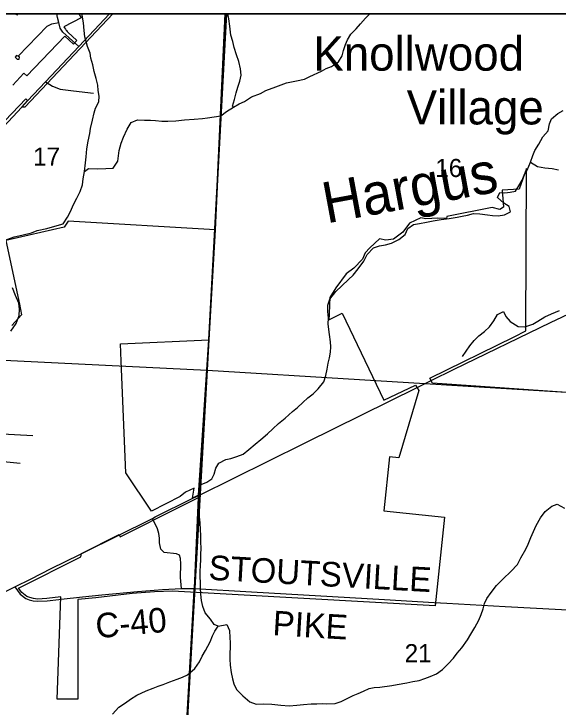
# Model space of a CAD drawing. Extents: x 0 to 42.5, y 0 to 22.
# Drawn here: x 3.26 to 3.889, y 20.099 to 20.9 of the extents above; entities that cross this region are included whole.
import ezdxf

# ---------------------------------------------------------------- set-up
doc = ezdxf.new("R2010")
doc.units = 0
for name, color, linetype in [('Default', 7, 'Continuous'), ('GM_X_City_Street', 7, 'Continuous'), ('GM_X_County_Road', 7, 'Continuous'), ('GM_X_County_Road_Text', 7, 'Continuous'), ('GM_X_Interchange_Ramps', 7, 'Continuous'), ('GM_X_Minor_River', 7, 'Continuous'), ('GM_X_Minor_River_Text', 7, 'Continuous'), ('GM_X_Section', 7, 'Continuous'), ('GM_X_Section_Text', 7, 'Continuous'), ('GM_X_State_Route', 7, 'Continuous'), ('GM_X_Township_Road', 7, 'Continuous'), ('GM_X_Unincorporated', 7, 'Continuous'), ('GM_X_Unincorporated_Text', 7, 'Continuous'), ('GM_X_US_Route', 7, 'Continuous'), ('SH_Cut_Line', 7, 'Continuous'), ('SH_Data', 7, 'Continuous')]:
    doc.layers.add(name, color=color, linetype=linetype)

msp = doc.modelspace()

# ---------------------------------------------------------------- linework, layer by layer
at = {"layer": 'Default'}
for points in [[(3.2411, 20.76833), (3.27355, 20.80191), (3.27571, 20.79986), (3.26896, 20.79269), (3.27265, 20.79246), (3.37429, 20.9), (3.33472, 20.9), (3.3375, 20.89547), (3.3176, 20.88509), (3.31838, 20.88375), (3.3193, 20.88237), (3.31984, 20.88169), (3.32051, 20.88084), (3.32148, 20.87978), (3.32233, 20.87894), (3.33264, 20.86917), (3.32881, 20.86498), (3.31884, 20.87442), (3.27482, 20.82825), (3.27137, 20.83149), (3.2584, 20.81768)], [(4.00978, 20.45475), (3.74365, 20.47336), (3.7405, 20.47906), (3.83808, 20.52698), (3.85138, 20.53367), (3.85232, 20.72132), (3.84367, 20.69748), (3.82404, 20.69631), (3.82568, 20.67669), (3.82124, 20.67411), (3.81259, 20.67622), (3.76025, 20.66594), (3.75987, 20.6636), (3.74959, 20.66407), (3.73604, 20.66337), (3.7302, 20.6643), (3.71711, 20.65822), (3.70917, 20.64794), (3.69842, 20.63976), (3.68954, 20.6386), (3.68229, 20.64), (3.67108, 20.62972), (3.6657, 20.62387), (3.66266, 20.61663), (3.65262, 20.60611), (3.64374, 20.59957), (3.63205, 20.58368), (3.62481, 20.57247), (3.62457, 20.56405), (3.62434, 20.55307), (3.62364, 20.54676), (3.63906, 20.55424), (3.6872, 20.45369), (3.72412, 20.47121), (3.72782, 20.46511), (3.70483, 20.38711), (3.69408, 20.38843), (3.68752, 20.32599), (3.75748, 20.31864), (3.74672, 20.21626), (3.44312, 20.23308), (3.42248, 20.23249), (3.39652, 20.23042), (3.35444, 20.22544), (3.33357, 20.2236), (3.33356, 20.10854), (3.30981, 20.10854), (3.31398, 20.22648), (3.29803, 20.22467), (3.28725, 20.22405), (3.28256, 20.22458), (3.27824, 20.2257), (3.27489, 20.22715), (3.2688, 20.23176), (3.26515, 20.23666), (3.33718, 20.27273), (3.33776, 20.27671), (3.38143, 20.29841), (3.38253, 20.29579), (3.45331, 20.33129), (3.47315, 20.34124), (3.47328, 20.34399), (3.46615, 20.34046), (3.46806, 20.35207), (3.45818, 20.34746), (3.45205, 20.34247), (3.41868, 20.32574), (3.38918, 20.36973), (3.38374, 20.49883), (3.3829, 20.51877), (3.48511, 20.52333), (3.49253, 20.65067), (3.32237, 20.66037), (3.31781, 20.65352), (3.25043, 20.6381), (3.2661, 20.56466), (3.2687, 20.55245), (3.25728, 20.53989)]]:
    msp.add_lwpolyline(points, dxfattribs=at)
at = {"layer": 'GM_X_City_Street'}
for points in [[(3.16393, 20.41928), (3.19651, 20.41749), (3.28161, 20.41282)], [(3.1975, 20.38464), (3.25158, 20.38246), (3.26694, 20.38101)]]:
    msp.add_lwpolyline(points, dxfattribs=at)
at = {"layer": 'GM_X_County_Road'}
msp.add_line((3.3143, 20.22385), (3.33918, 20.22644), dxfattribs=at)
for points in [[(3.26093, 20.2382), (3.26722, 20.22981), (3.2738, 20.22483), (3.27757, 20.22319), (3.28223, 20.22198), (3.2873, 20.22141), (3.29835, 20.22204), (3.31181, 20.2236), (3.3143, 20.22385)], [(3.33918, 20.22644), (3.36158, 20.22877), (3.40255, 20.23263), (3.43172, 20.23516), (3.45359, 20.23608), (3.46349, 20.2362)], [(3.46349, 20.2362), (3.46843, 20.23625), (3.53455, 20.23246), (3.68806, 20.22342), (3.7457, 20.22016)], [(3.7457, 20.22016), (3.7601, 20.21934), (3.82766, 20.21554), (3.92139, 20.21048), (3.97179, 20.2072), (3.97328, 20.20712)]]:
    msp.add_lwpolyline(points, dxfattribs=at)
at = {"layer": 'GM_X_Interchange_Ramps'}
for points in [[(3.11995, 19.00104), (3.37078, 18.98615), (3.37742, 18.98467), (3.39197, 18.98393), (3.40756, 19.23914), (3.43715, 19.68433), (3.46832, 20.23391), (3.46843, 20.23651), (3.47315, 20.34124), (3.47328, 20.34399), (3.48511, 20.52333), (3.49253, 20.65067), (3.50401, 20.9), (2.3057, 20.9)], [(5.48884, 19.405), (5.50057, 19.55251), (5.51061, 19.66936), (5.5156, 19.73605), (5.52526, 19.85376), (5.53536, 19.98472), (5.54606, 20.11658), (5.56474, 20.34561), (5.56563, 20.35496), (5.56586, 20.35729), (5.60252, 20.8068), (5.60957, 20.9), (3.50401, 20.9), (3.49253, 20.65067), (3.48511, 20.52333), (3.47328, 20.34399), (3.47315, 20.34124), (3.46843, 20.23651), (3.46832, 20.23391), (3.43715, 19.68433), (3.40756, 19.23914)]]:
    msp.add_lwpolyline(points, dxfattribs=at)
at = {"layer": 'GM_X_Minor_River'}
for points in [[(3.34425, 20.74395), (3.34563, 20.75287), (3.34739, 20.76179), (3.34819, 20.76749), (3.35071, 20.77717), (3.35246, 20.78552), (3.3542, 20.79102), (3.35804, 20.7984), (3.35846, 20.80486), (3.35736, 20.81133), (3.35683, 20.8178), (3.35498, 20.82541), (3.35257, 20.83341), (3.35091, 20.84102), (3.34887, 20.84882), (3.34815, 20.85472), (3.34497, 20.86234), (3.34163, 20.87339), (3.34091, 20.88061), (3.34021, 20.88955), (3.33856, 20.89868), (3.33813, 20.9)], [(3.34125, 20.71793), (3.3462, 20.72151), (3.35643, 20.72088), (3.3661, 20.72119), (3.37463, 20.72171), (3.37979, 20.72966), (3.38078, 20.73611), (3.38138, 20.742), (3.38371, 20.75073), (3.38659, 20.75755), (3.39082, 20.76684), (3.39522, 20.7746), (3.40282, 20.77759), (3.41078, 20.77716), (3.41779, 20.7773), (3.42347, 20.77689), (3.43066, 20.77608), (3.43768, 20.77604), (3.44696, 20.77655), (3.45682, 20.77762), (3.46801, 20.77831), (3.47787, 20.7792), (3.48355, 20.77973), (3.49114, 20.78101), (3.49892, 20.78229), (3.50558, 20.78738), (3.51357, 20.79227), (3.52022, 20.79603), (3.5263, 20.79884), (3.53429, 20.8043), (3.54493, 20.80785), (3.55101, 20.81161), (3.5626, 20.81571), (3.57494, 20.82019), (3.58651, 20.82259), (3.59562, 20.82462), (3.6017, 20.82762), (3.61538, 20.83362), (3.62089, 20.837), (3.62678, 20.83925), (3.63477, 20.84452), (3.63918, 20.85171), (3.64073, 20.85759), (3.64304, 20.86461), (3.64535, 20.8701), (3.64937, 20.87673), (3.65528, 20.88258), (3.66043, 20.88863), (3.66634, 20.89506), (3.67103, 20.9)], [(3.51357, 20.79227), (3.51263, 20.79323), (3.51495, 20.80101), (3.5167, 20.80879), (3.51863, 20.81524), (3.52095, 20.82244), (3.52232, 20.82908), (3.52179, 20.83669), (3.51976, 20.84487), (3.51716, 20.85268), (3.51455, 20.86125), (3.5127, 20.8681), (3.51066, 20.87534), (3.50921, 20.88561), (3.50812, 20.89417), (3.50693, 20.9)], [(3.84328, 20.70122), (3.84711, 20.70803), (3.84941, 20.71353), (3.85305, 20.71959), (3.85671, 20.72888), (3.85941, 20.73627), (3.8619, 20.74215), (3.86631, 20.74953), (3.87128, 20.75805), (3.8772, 20.76485), (3.87895, 20.77301), (3.88107, 20.77889), (3.88831, 20.78474), (3.89478, 20.7885)], [(3.24848, 20.63814), (3.26026, 20.64244), (3.26899, 20.64447), (3.28019, 20.64706), (3.28664, 20.64968), (3.29784, 20.65208), (3.30714, 20.65468), (3.31682, 20.65747), (3.3216, 20.66523), (3.32505, 20.67167), (3.32851, 20.67963), (3.33273, 20.68701), (3.33657, 20.69497), (3.33907, 20.70236), (3.34006, 20.70939), (3.34125, 20.71793), (3.34264, 20.72781), (3.34325, 20.73502), (3.34425, 20.74395)], [(3.85671, 20.72888), (3.86482, 20.7235), (3.87353, 20.72231), (3.88186, 20.7213), (3.88905, 20.71993)], [(3.4959, 20.1928), (3.49137, 20.19473), (3.48705, 20.20084), (3.48084, 20.20829), (3.47823, 20.21553), (3.47675, 20.22238), (3.47604, 20.2298), (3.47552, 20.23702), (3.47536, 20.24272), (3.47522, 20.25014), (3.47525, 20.25584), (3.47548, 20.26287), (3.47571, 20.26933), (3.47575, 20.27617), (3.47617, 20.28206), (3.47603, 20.29042), (3.47569, 20.29726), (3.47536, 20.30449), (3.47521, 20.3119), (3.4745, 20.31894), (3.47416, 20.32578), (3.4742, 20.33167), (3.47405, 20.33775), (3.47408, 20.34346), (3.47431, 20.34992), (3.47624, 20.35655), (3.48289, 20.35898), (3.4886, 20.36275), (3.49128, 20.36824), (3.49322, 20.37507), (3.49667, 20.38094), (3.50484, 20.38526), (3.51072, 20.38655), (3.51737, 20.38879), (3.52496, 20.3914), (3.53144, 20.39687), (3.53868, 20.4029), (3.54515, 20.40837), (3.55277, 20.41498), (3.55906, 20.42083), (3.56554, 20.42687), (3.57316, 20.43309), (3.58173, 20.44083), (3.58763, 20.44535), (3.59373, 20.4512), (3.59963, 20.45629), (3.60554, 20.4612), (3.61145, 20.46686), (3.61794, 20.4748), (3.62026, 20.48239), (3.62182, 20.4896), (3.62318, 20.49643), (3.62474, 20.50269), (3.62553, 20.50915), (3.62595, 20.51523), (3.62561, 20.52131), (3.62471, 20.52949), (3.6238, 20.53558), (3.62308, 20.54204), (3.6235, 20.5485), (3.6226, 20.5563), (3.62264, 20.56352), (3.62477, 20.57035), (3.63184, 20.57943), (3.6387, 20.58603), (3.64651, 20.5932), (3.65203, 20.59811), (3.65757, 20.6053), (3.66407, 20.61438), (3.6681, 20.62214), (3.67534, 20.6297), (3.68218, 20.63193), (3.68939, 20.63303), (3.69622, 20.63507), (3.70477, 20.6392), (3.71201, 20.64524), (3.71527, 20.65225), (3.72155, 20.65677), (3.72857, 20.65786), (3.73653, 20.65933), (3.74431, 20.66099), (3.75361, 20.66264), (3.76271, 20.66372), (3.772, 20.665), (3.77807, 20.66629), (3.78395, 20.66758), (3.79117, 20.66943), (3.79836, 20.66901), (3.80726, 20.66781), (3.81313, 20.6672), (3.81957, 20.66659), (3.82678, 20.66787), (3.83362, 20.67125), (3.83233, 20.67753), (3.82591, 20.68118), (3.81856, 20.68769), (3.82144, 20.69375), (3.82712, 20.69334), (3.83338, 20.69406), (3.83964, 20.69535), (3.84328, 20.70122)], [(3.25638, 20.53357), (3.2623, 20.54227), (3.26596, 20.55156), (3.26619, 20.55878), (3.26567, 20.56563), (3.26174, 20.57458), (3.25801, 20.58354)], [(3.77823, 20.50418), (3.78262, 20.51042), (3.78683, 20.51648), (3.79179, 20.52253), (3.79713, 20.52819), (3.8036, 20.53309), (3.80932, 20.53838), (3.81448, 20.54557), (3.81869, 20.55257), (3.82572, 20.55614), (3.82853, 20.55023), (3.83342, 20.54449), (3.84248, 20.53892), (3.85044, 20.53849), (3.85936, 20.54148), (3.86525, 20.54486), (3.87343, 20.54994), (3.88103, 20.55369), (3.89034, 20.55724)], [(3.71379, 20.12736), (3.721, 20.12883), (3.72801, 20.13012), (3.73485, 20.13235), (3.74074, 20.13441), (3.74814, 20.13759), (3.75518, 20.14248), (3.76167, 20.14909), (3.76777, 20.15571), (3.77197, 20.16138), (3.77751, 20.16781), (3.7842, 20.17708), (3.78802, 20.18332), (3.79262, 20.19128), (3.79722, 20.1998), (3.79991, 20.20624), (3.80204, 20.21288), (3.80359, 20.21895), (3.80628, 20.22482), (3.81143, 20.23144), (3.81755, 20.23958), (3.82517, 20.24732), (3.83413, 20.25581), (3.84176, 20.26413), (3.84578, 20.27151), (3.85134, 20.28174), (3.85403, 20.28742), (3.8573, 20.29519), (3.86018, 20.30221), (3.86325, 20.30884), (3.86823, 20.31774), (3.87396, 20.3253), (3.88139, 20.33134), (3.88766, 20.33377), (3.89634, 20.32915)], [(3.37382, 20.09096), (3.38107, 20.09928), (3.38868, 20.10417), (3.39439, 20.1085), (3.402, 20.11302), (3.41283, 20.11789), (3.42062, 20.12107), (3.4267, 20.12331), (3.43239, 20.12536), (3.44018, 20.12835), (3.44835, 20.13153), (3.4548, 20.13377), (3.46032, 20.1364), (3.46908, 20.14375), (3.47424, 20.15151), (3.4775, 20.15814), (3.48133, 20.16458), (3.48651, 20.17443), (3.48939, 20.18144), (3.49189, 20.18694), (3.4959, 20.1928), (3.50577, 20.19483), (3.50894, 20.18759), (3.50927, 20.17941), (3.50981, 20.1739), (3.50978, 20.16839), (3.50935, 20.16117), (3.50931, 20.15452), (3.50984, 20.14748), (3.51073, 20.13911), (3.5124, 20.13207), (3.51407, 20.12598), (3.51725, 20.11969), (3.5244, 20.11223), (3.53251, 20.10515), (3.53969, 20.10263), (3.5486, 20.10314), (3.55788, 20.10251), (3.56849, 20.1013), (3.57777, 20.10086), (3.58687, 20.10138), (3.59445, 20.10228), (3.60355, 20.10298), (3.60999, 20.10313), (3.61606, 20.10328), (3.62155, 20.10305), (3.63103, 20.10337), (3.63805, 20.10561), (3.64508, 20.10917), (3.65174, 20.11274), (3.65782, 20.11498), (3.6639, 20.11779), (3.67036, 20.1206), (3.67605, 20.12171), (3.68268, 20.12243), (3.69671, 20.12424), (3.70278, 20.12515), (3.71379, 20.12736)]]:
    msp.add_lwpolyline(points, dxfattribs=at)
at = {"layer": 'GM_X_Section'}
for points in [[(2.97397, 20.51334), (3.48334, 20.48855), (3.4546, 19.98469), (2.94222, 20.01405)], [(3.48334, 20.48855), (4.01124, 20.45591), (3.97586, 19.95227), (3.4546, 19.98469)]]:
    msp.add_lwpolyline(points, close=True, dxfattribs=at)
at = {"layer": 'GM_X_State_Route'}
msp.add_line((3.2688, 20.79213), (3.27571, 20.79948), dxfattribs=at)
for points in [[(3.27571, 20.79948), (3.29644, 20.82154), (3.33468, 20.86223), (3.37048, 20.9)], [(3.17387, 20.72882), (3.21945, 20.75311), (3.24254, 20.76419), (3.2688, 20.79213)]]:
    msp.add_lwpolyline(points, dxfattribs=at)
at = {"layer": 'GM_X_Township_Road'}
for points in [[(3.26089, 20.9), (3.26402, 20.89904), (3.26424, 20.9)], [(3.33468, 20.86223), (3.3162, 20.87896), (3.31338, 20.88354), (3.31168, 20.8901), (3.31022, 20.89572), (3.30946, 20.9)], [(3.26458, 20.85113), (3.26286, 20.85206), (3.26139, 20.85007), (3.26354, 20.84749), (3.26596, 20.8476), (3.26612, 20.84986), (3.26468, 20.85113), (3.29821, 20.88591), (3.30373, 20.88854), (3.31168, 20.8901)], [(3.29644, 20.82154), (3.30426, 20.8165), (3.31336, 20.81303), (3.32854, 20.81123), (3.3517, 20.80843)], [(3.45359, 20.23608), (3.45219, 20.24907), (3.45285, 20.26484), (3.4525, 20.27092), (3.45139, 20.27473), (3.44779, 20.27646), (3.43355, 20.27788), (3.42969, 20.28168), (3.42826, 20.28896), (3.4279, 20.29445), (3.42726, 20.29973), (3.42562, 20.3053), (3.41997, 20.31725)]]:
    msp.add_lwpolyline(points, dxfattribs=at)
at = {"layer": 'GM_X_Unincorporated'}
for points in [[(3.50543, 20.9), (2.99274, 20.9), (2.97397, 20.51334), (3.48334, 20.48855)], [(4.04384, 20.9), (3.50543, 20.9), (3.48334, 20.48855), (4.01124, 20.45591)]]:
    msp.add_lwpolyline(points, close=True, dxfattribs=at)
at = {"layer": 'GM_X_US_Route'}
for p, q in [((3.72597, 20.46833), (3.74212, 20.47632)), ((3.47339, 20.34373), (3.59496, 20.40355)), ((3.46667, 20.3404), (3.47339, 20.34373)), ((3.3382, 20.27661), (3.38176, 20.29825)), ((3.33586, 20.27544), (3.3382, 20.27661)), ((3.30308, 20.25915), (3.33586, 20.27544)), ((3.27966, 20.24751), (3.30308, 20.25915))]:
    msp.add_line(p, q, dxfattribs=at)
for points in [[(3.74212, 20.47632), (3.76859, 20.48941), (3.88009, 20.54365), (3.91506, 20.56001), (3.95465, 20.57598), (4.02129, 20.60145)], [(3.59496, 20.40355), (3.5981, 20.40509), (3.72597, 20.46833)], [(3.38176, 20.29825), (3.41688, 20.31571), (3.41997, 20.31725), (3.42322, 20.31886), (3.46667, 20.3404)], [(3.21026, 20.21284), (3.26093, 20.2382), (3.27966, 20.24751)]]:
    msp.add_lwpolyline(points, dxfattribs=at)
at = {"layer": 'SH_Cut_Line'}
msp.add_lwpolyline([(5.48884, 19.405), (5.50057, 19.55251), (5.51061, 19.66936), (5.5156, 19.73605), (5.52526, 19.85376), (5.53536, 19.98472), (5.54606, 20.11658), (5.56474, 20.34561), (5.56563, 20.35496), (5.56586, 20.35729), (5.60252, 20.8068), (5.60957, 20.9), (2.1, 20.9), (2.1, 16.00757)], dxfattribs=at)
at = {"layer": 'SH_Data'}
msp.add_line((2.1, 20.9), (8.9, 20.9), dxfattribs=at)

# ---------------------------------------------------------------- texts
at = {"layer": 'GM_X_County_Road_Text'}
for s, height, rotation, p in [('STOUTSVILLE', 0.0284091, 356.80275, (3.48435, 20.24641)), ('C-40', 0.028409, 5.40967, (3.35552, 20.17861)), ('PIKE', 0.028409, 356.59787, (3.5583, 20.18233))]:
    msp.add_text(s, height=height, rotation=rotation, dxfattribs=at).set_placement(p)
at = {"layer": 'GM_X_Minor_River_Text'}
msp.add_text('Hargus', height=0.047347, rotation=10.53116, dxfattribs=at).set_placement((3.62111, 20.65779))
at = {"layer": 'GM_X_Section_Text'}
for s, p in [('17', (3.28203, 20.7247)), ('16', (3.74683, 20.71152)), ('21', (3.71141, 20.15105))]:
    msp.add_text(s, height=0.020928, rotation=0.00001, dxfattribs=at).set_placement(p)
at = {"layer": 'GM_X_Unincorporated_Text'}
for s, p in [('Knollwood', (3.60578, 20.83439)), ('Village', (3.7137, 20.7723))]:
    msp.add_text(s, height=0.039489, rotation=0.00001, dxfattribs=at).set_placement(p)

doc.saveas('drawing.dxf')
